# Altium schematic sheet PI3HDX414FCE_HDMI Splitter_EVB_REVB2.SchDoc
size 317 x 203 mm
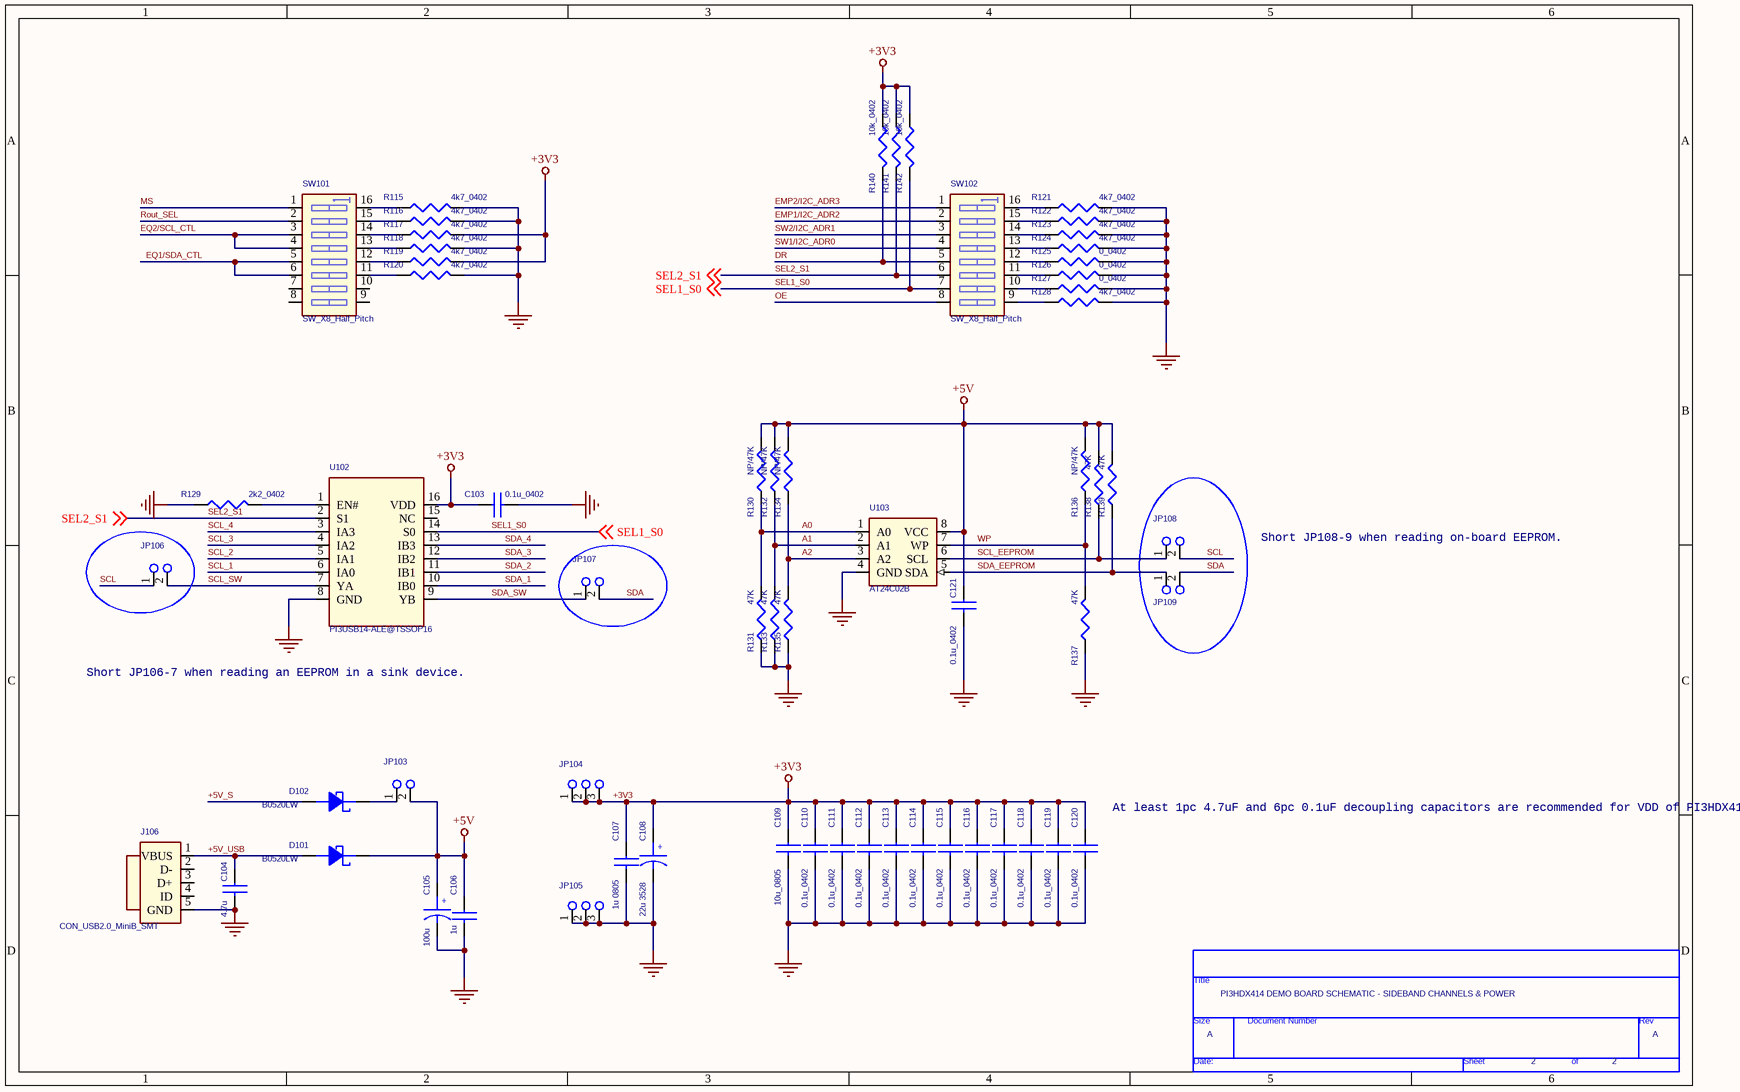
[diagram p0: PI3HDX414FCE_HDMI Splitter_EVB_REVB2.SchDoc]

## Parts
*  Page Count: 2  Page Size: A  Title: PI3HDX414 DEMO BOARD SCHEMATIC - SIDEBAND CHANNELS & POWER  (hidden comment: TitleBlock0)  (graphical)
C103  0.1u_0402  [CC_0402]
C104  4.7u  [CAP@CC_0805]
C105  100u  [CAP@CT_7343]
C106  1u  [CAP@CC_0805]
C107  1u 0805  [CAP@CC_0805]
C108  22u 3528  [CAP@CT_3528]
C109  10u_0805  [CC_0805]
C110  0.1u_0402  [CC_0402]
C111  0.1u_0402  [CC_0402]
C112  0.1u_0402  [CC_0402]
C113  0.1u_0402  [CC_0402]
C114  0.1u_0402  [CC_0402]
C115  0.1u_0402  [CC_0402]
C116  0.1u_0402  [CC_0402]
C117  0.1u_0402  [CC_0402]
C118  0.1u_0402  [CC_0402]
C119  0.1u_0402  [CC_0402]
C120  0.1u_0402  [CC_0402]
C121  0.1u_0402  [CC_0402]
D101  B0520LW  [D@SOD-123]
D102  B0520LW  [D@SOD-123]
J106  CON_USB2.0_MiniB_SMT  [CON_USB2.0_MiniB_SMT]
JP103  2x1 Pin Header  [2x1 Pin Header]  (value not drawn)
JP104  3x1 Pin Header  [3x1 Pin Header]  (value not drawn)
JP105  3x1 Pin Header  [3x1 Pin Header]  (value not drawn)
JP106  2x1 Pin Header  [2x1 Pin Header]  (value not drawn)
JP107  2x1 Pin Header  [2x1 Pin Header]  (value not drawn)
JP108  2x1 Pin Header  [2x1 Pin Header]  (value not drawn)
JP109  2x1 Pin Header  [2x1 Pin Header]  (value not drawn)
R115  4k7_0402  [R_0402]
R116  4k7_0402  [R_0402]
R117  4k7_0402  [R_0402]
R118  4k7_0402  [R_0402]
R119  4k7_0402  [R_0402]
R120  4k7_0402  [R_0402]
R121  4k7_0402  [R_0402]
R122  4k7_0402  [R_0402]
R123  4k7_0402  [R_0402]
R124  4k7_0402  [R_0402]
R125  0_0402  [R_0402]
R126  0_0402  [R_0402]
R127  0_0402  [R_0402]
R128  4k7_0402  [R_0402]
R129  2k2_0402  [R_0402]
R130  NP/47K  [RES@R_0402]
R131  47K  [RES@R_0402]
R132  NP/47K  [RES@R_0402]
R133  47K  [RES@R_0402]
R134  NP/47K  [RES@R_0402]
R135  47K  [RES@R_0402]
R136  NP/47K  [RES@R_0402]
R137  47K  [RES@R_0402]
R138  47K  [RES@R_0402]
R139  47K  [RES@R_0402]
R140  10k_0402  [R_0402]
R141  10k_0402  [R_0402]
R142  10k_0402  [R_0402]
SW101  SW_X8_Half_Pitch  [SW_X8_Half_Pitch]
SW102  SW_X8_Half_Pitch  [SW_X8_Half_Pitch]
U102  PI3USB14-ALE@TSSOP16  [TSSOP16]
U103  AT24C02B  [SOIC8]

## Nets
+3V3: C103.1 C107.1 C108.1 C109.1 C110.1 C111.1 C112.1 C113.1 C114.1 C115.1 C116.1 C117.1 C118.1 C119.1 C120.1 JP104.1 JP104.2 JP104.3 R117.2 R119.2 R140.1 R141.1 R142.1 U102.16(VDD)
+5V: C105.1 C106.1 C121.1 D101.2 JP103.2 R130.2 R132.2 R134.2 R136.2 R138.2 R139.2 U103.8(VCC)
GND: C103.2 C104.2 C105.2 C106.2 C107.2 C108.2 C109.2 C110.2 C111.2 C112.2 C113.2 C114.2 C115.2 C116.2 C117.2 C118.2 C119.2 C120.2 C121.2 J106.5(GND) JP105.1 JP105.2 JP105.3 R115.2 R116.2 R118.2 R120.2 R121.2 R122.2 R123.2 R124.2 R125.2 R126.2 R127.2 R128.2 R129.1 R131.1 R133.1 R135.1 R137.1 U102.8(GND) U103.4(GND)
+5V_S: D102.1
+5V_USB: C104.1 D101.1 J106.1(VBUS)
A0: R130.1 R131.2 U103.1(A0)
A1: R132.1 R133.2 U103.2(A1)
A2: R134.1 R135.2 U103.3(A2)
DR: R140.2 SW102.5(A5)
EMP1/I2C_ADR2: SW102.2(A2)
EMP2/I2C_ADR3: SW102.1(A1)
EQ1/SDA_CTL: SW101.5(A5) SW101.6(A6)
EQ2/SCL_CTL: SW101.3(A3) SW101.4(A4)
MS: SW101.1(A1)
OE: SW102.8(A8)
Rout_SEL: SW101.2(A2)
SCL: JP106.1 JP108.2
SCL_1: U102.6(IA0)
SCL_2: U102.5(IA1)
SCL_3: U102.4(IA2)
SCL_4: U102.3(IA3)
SCL_EEPROM: JP108.1 R138.1 U103.6(SCL)
SCL_SW: JP106.2 U102.7(YA)
SDA: JP107.2 JP109.2
SDA_1: U102.10(IB0)
SDA_2: U102.11(IB1)
SDA_3: U102.12(IB2)
SDA_4: U102.13(IB3)
SDA_EEPROM: JP109.1 R139.1 U103.5(SDA)
SDA_SW: JP107.1 U102.9(YB)
SEL1_S0: R142.2 SW102.7(A7) U102.14(S0) ; off-sheet SEL1_S0
SEL2_S1: R141.2 SW102.6(A6) U102.2(S1) ; off-sheet SEL2_S1
SW1/I2C_ADR0: SW102.4(A4)
SW2/I2C_ADR1: SW102.3(A3)
WP: R136.1 R137.2 U103.7(WP)
NetD102_2: D102.2 JP103.1
NetR115_1: R115.1 SW101.16(B1)
NetR116_1: R116.1 SW101.15(B2)
NetR117_1: R117.1 SW101.14(B3)
NetR118_1: R118.1 SW101.13(B4)
NetR119_1: R119.1 SW101.12(B5)
NetR120_1: R120.1 SW101.11(B6)
NetR121_1: R121.1 SW102.16(B1)
NetR122_1: R122.1 SW102.15(B2)
NetR123_1: R123.1 SW102.14(B3)
NetR124_1: R124.1 SW102.13(B4)
NetR125_1: R125.1 SW102.12(B5)
NetR126_1: R126.1 SW102.11(B6)
NetR127_1: R127.1 SW102.10(B7)
NetR128_1: R128.1 SW102.9(B8)
NetR129_2: R129.2 U102.1(EN#)

Not connected (* = marked no-connect by the designer): J106 2(D-) 3(D+) 4(ID); SW101 7(A7) 8(A8) 9(B8) 10(B7); U102 15(NC)

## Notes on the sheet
- Short JP108-9 when reading on-board EEPROM.
- Short JP106-7 when reading an EEPROM in a sink device.
- At least 1pc 4.7uF and 6pc 0.1uF decoupling capacitors are recommended for VDD of PI3HDX414.Each decoupling capacitor should be connected toPCB power plane via shortest path.

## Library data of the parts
C103 C110-C121 = C_0.1u_0402
C104 C106 C107 = CHIP CAP0805
C105 = 100UF 7343_1
C108 = 22UF 3528
C109 = C_10u_0805
D101 D102 = SchottkyDiode@SOD-123_1
R115-R129 R140-R142 = R_0402_Dup1
R130-R139 = CHIP RES0402_0
U103 = 24C02@SOIC8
